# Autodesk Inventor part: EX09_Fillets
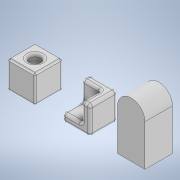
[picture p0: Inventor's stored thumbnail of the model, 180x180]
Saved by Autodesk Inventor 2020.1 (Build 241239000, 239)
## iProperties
Created: 2019-10
Part Number: EX09_Fillets
Material: Generic
Document SubType Name: Modeling
Designer: Synergysoft Dell02
Density: 1 g/cm^3
Appearance: Default
Author: Synergysoft Dell02
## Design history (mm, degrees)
sketch "Sketch1"
  geometry: L1 (25, -25)-(-25, -25); L2 (-25, -25)-(-25, 25); L3 (-25, 25)-(25, 25); L4 (25, 25)-(25, -25); L5 (25, -25)-(-25, 25); L6 (-25, -25)-(25, 25); L7 (-75, -25)-(-125, -25); L8 (-125, -25)-(-125, 25); L9 (-125, 25)-(-75, 25); L10 (-75, 25)-(-75, -25); L11 (-75, -25)-(-125, 25); L12 (-125, -25)-(-75, 25); L13 (-175, -25)-(-225, -25); L14 (-225, -25)-(-225, 25); L15 (-225, 25)-(-175, 25); L16 (-175, 25)-(-175, -25); L17 (-175, -25)-(-225, 25); L18 (-225, -25)-(-175, 25); 7 further points
  constraints: 36 end point, 10 midpoint, 6 parallel, 3 horizontal, 3 perpendicular, 2 horizontal alignment
  dimensions: "d0" = 50 distance of L2.end L3.end; "d1" = 50 distance of L1.end L2.end; "d2" = 50 distance of L8.end L9.end; "d3" = 50 distance of L7.end L8.end; "d4" = 50 distance of L14.end L15.end; "d5" = 50 distance of L13.end L14.end; "d6" = 100 distance of point (-100, 0) point (0, 0); "d7" = 100 distance of point (-200, 0) point (-100, 0)
extrude "Extrusion1" new body sketch "Sketch1" distance "d8" = 50; taper "d9" = 0 deg
sketch "Sketch2"
  geometry: C1 r 10 at (0, 0); 1 further point
  constraints: 1 centre point, 1 coincident
  dimensions: "d14" = 20 diameter of C1
extrude "Extrusion4" cut sketch "Sketch2" distance "d15" = 20; taper "d16" = 0 deg
extrude "Extrusion2" new body sketch "Sketch1" distance "d10" = 50; taper "d11" = 0 deg
sketch "Sketch3"
  geometry: L1 (75, 25)-(75, -25) reference; L2 (75, -25)-(110, -25); L3 (110, -25)-(110, 10); L4 (110, 10)-(75, 10); L5 (75, 10)-(75, -25); 2 further points
  constraints: 8 end point, 2 parallel, 1 horizontal, 1 perpendicular
  dimensions: "d17" = 35 distance of L4.end L3.end; "d18" = 35 distance of L3.end L2.end
extrude "Extrusion5" cut sketch "Sketch3" distance "d19" = 35; taper "d20" = 0 deg
extrude "Extrusion3" new body sketch "Sketch1" distance "d12" = 100; taper "d13" = 0 deg
fillet "Fillet1" dims "d21" = 5
fillet "Fillet2" dims "d22" = 3
fillet "Fillet3" dims "d23" = 3, "d24" = 3
fillet "Fillet4" dims "d25" = 5
fillet "Fillet5" dims "d26" = 5
fillet "Fillet6" dims "d27" = 5
fillet "Fillet7" dims "d28" = 5, "d29" = 5
fillet "Fillet8"
body "Solid1"
body "Solid2"
body "Solid3"
